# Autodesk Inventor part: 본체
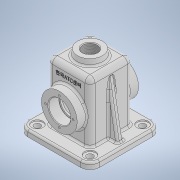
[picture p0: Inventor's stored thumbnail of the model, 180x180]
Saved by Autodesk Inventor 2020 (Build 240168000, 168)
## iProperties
Created: 2021-07
Part Number: 본체
Material: 일반
Document SubType Name: Modeling
Designer: Owner
Density: 1 g/cm^3
Appearance: 기본값
Mass: 278.26 g
Surface Area: 858.222 cm^2
Volume: 278.26 cm^3
Author: Owner
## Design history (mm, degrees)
sketch "스케치1"
  geometry: L1 (-34, 105)-(34, 105); L2 (34, 105)-(34, 0); L3 (34, 0)-(-34, 0); L4 (-34, 0)-(-34, 105); L5 (-34, 105)-(34, 0); L6 (34, 105)-(-34, 0); 4 further points
  constraints: 12 end point, 4 midpoint, 2 parallel, 1 coincident, 1 horizontal, 1 perpendicular, 1 vertical alignment
  dimensions: "d0" = 68 distance of L2.end L3.end; "d1" = 105 distance of L1.end L2.end
extrude "돌출1" new body sketch "스케치1" stored distance "d2" = 68; taper "d3" = 0 deg
fillet "모깎기1" dims "d4" = 8
fillet "모깎기2" dims "d5" = 8
feature "쉘1" dims "d6" = 5
node "작업 평면1"
sketch "스케치2"
  geometry: C1 r 28.5 at (0, 52); 1 further point
  constraints: 1 centre point, 1 vertical alignment
  dimensions: "d8" = 57 diameter of C1; "d9" = 52 distance of point (0, 0) C1.centre
extrude "돌출2" join sketch "스케치2" stored distance "d10" = 15; taper "d11" = 0 deg
sketch "스케치3"
  geometry: C1 r 28.5 at (0, 0) reference; 2 further points
  constraints: 1 coincident
hole "구멍1" sketch "스케치3" at (0, 0) diameter "d12" = 30; stored, may be unused: countersink angle "d16" = 90 deg, drill point angle "d18" = 0 deg; dims "d13" = 8, "d14" = 35, "d15" = 17, "d17" = 20
sketch "스케치4"
  geometry: C1 r 17.5 at (0, 0) reference; 2 further points
  constraints: 1 vertical alignment
  dimensions: "d19" = 22 distance of C1.centre point (0, 22)
hole "구멍2" sketch "스케치4" at (0, 22) diameter "d20" = 3.242; stored, may be unused: countersink angle "d24" = 90 deg, drill point angle "d26" = 118 deg; dims "d21" = 8, "d22" = 35, "d23" = 17, "d25" = 10
sketch "스케치5"
  geometry: L1 (57, 57)-(-57, 57); L2 (-57, 57)-(-57, -57); L3 (-57, -57)-(57, -57); L4 (57, -57)-(57, 57); L5 (57, 57)-(-57, -57); L6 (-57, 57)-(57, -57); L7 (26, 29)-(-26, 29) reference; L8 (-29, 26)-(-29, -26) reference; L9 (-26, -29)-(26, -29) reference; L10 (29, -26)-(29, 26) reference; L11 (34, -26)-(34, 26) reference; L12 (-26, -34)-(26, -34) reference; L13 (-34, -26)-(-34, 26) reference; L14 (26, 34)-(-26, 34) reference; A1 r 3 centre (26, 26) between (29, 26) and (26, 29) reference; A2 r 3 centre (-26, 26) between (-26, 29) and (-29, 26) reference; A3 r 3 centre (-26, -26) between (-29, -26) and (-26, -29) reference; A4 r 3 centre (26, -26) between (26, -29) and (29, -26) reference; A5 r 8 centre (26, 26) between (34, 26) and (26, 34) reference; A6 r 8 centre (26, -26) between (26, -34) and (34, -26) reference; A7 r 8 centre (-26, -26) between (-34, -26) and (-26, -34) reference; A8 r 8 centre (-26, 26) between (-26, 34) and (-34, 26) reference; 1 further point
  constraints: 12 end point, 2 midpoint, 2 parallel, 1 horizontal, 1 perpendicular
  dimensions: "d30" = 114 distance of L3.end L2.end; "d31" = 114 distance of L2.end L1.end
extrude "돌출3" join sketch "스케치5" distance "d32" = 10; taper "d33" = 0 deg
fillet "모깎기3" dims "d34" = 15
node "작업 평면2"
sketch "스케치7"
  geometry: C1 r 20 at (26, 26); 1 further point
  constraints: 1 centre point, 1 coincident
  dimensions: "d43" = 40 diameter of C1
extrude "돌출4" join sketch "스케치7" distance "d44" = 10; taper "d45" = 8 deg
sketch "스케치8"
  geometry: C1 r 20 at (0, 0) reference; 2 further points
  constraints: 1 coincident
hole "구멍4" sketch "스케치8" at (0, 0) diameter "d46" = 22.83494; stored, may be unused: countersink angle "d50" = 90 deg, drill point angle "d52" = 118 deg; dims "d47" = 50, "d48" = 18, "d49" = 2, "d51" = 59.3
sketch "스케치9"
  geometry: L1 (49, 10)-(40.045, 60.789); L2 (57, 10)-(57, 0) reference; L3 (42, 10)-(57, 10) reference; 1 further point
  constraints: 2 end point, 1 point on line
  dimensions: "d53" = 10 deg angle of L2 L1; "d72" = 8 distance from line of L2 L1.start
feature "리브1" sketch "스케치9" dims "d55" = 1, "d56" = 10, "d57" = 0, "d58" = 0, "d59" = 1, "d60" = 1
chamfer "모따기1" distance "d61" = 1; stored, may be unused: second distance "d62" = 2, angle "d63" = 45 deg
fillet "모깎기4" dims "d64" = 0.3
fillet "모깎기5" dims "d65" = 3
fillet "모깎기6" dims "d66" = 3
fillet "모깎기7" dims "d67" = 3
fillet "모깎기8" dims "d68" = 3
sketch "스케치10"
  geometry: L1 (20, 115)-(-20, 115) reference; L2 (-42, 0)-(42, 0) reference; 3 further points
  constraints: 1 midpoint, 1 vertical alignment, 1 other
  dimensions: "d69" = 25 distance from line of L1 point (0, 90)
feature "엠보싱1" sketch "스케치10" dims "d0" = 68, "d1" = 105, "d70" = 0.5, "d71" = 0
sketch "스케치11"
  geometry: A1 r 15 centre (-42, 42) between (-42, 57) and (-57, 42) reference; A2 r 15 centre (-42, -42) between (-57, -42) and (-42, -57) reference; A3 r 15 centre (42, -42) between (42, -57) and (57, -42) reference; A4 r 15 centre (42, 42) between (57, 42) and (42, 57) reference; 5 further points
  constraints: 4 coincident
hole "구멍5" sketch "스케치11" at (-42, 42), (-42, -42), (42, -42), (42, 42) diameter "d73" = 10; stored, may be unused: countersink angle "d77" = 90 deg, drill point angle "d79" = 118 deg; dims "d74" = 50, "d75" = 18, "d76" = 2, "d78" = 59.3
chamfer "모따기2" distance "d80" = 1; stored, may be unused: second distance "d81" = 2, angle "d82" = 45 deg
node "솔리드1"
pattern_circular "원형 패턴1" dims angle "d28" = 360 deg
mirror "미러1"
mirror "미러2"
node "투영된 루프1"
feature "A9D066F2-1C7D-4E18-AEED-F7BC21143FA4" dims "d12" = 30, "d13" = 8, "d14" = 35, "d15" = 17, "d16" = 90 deg, "d17" = 20, "d18" = 0
other parameters: "d7" = 15
